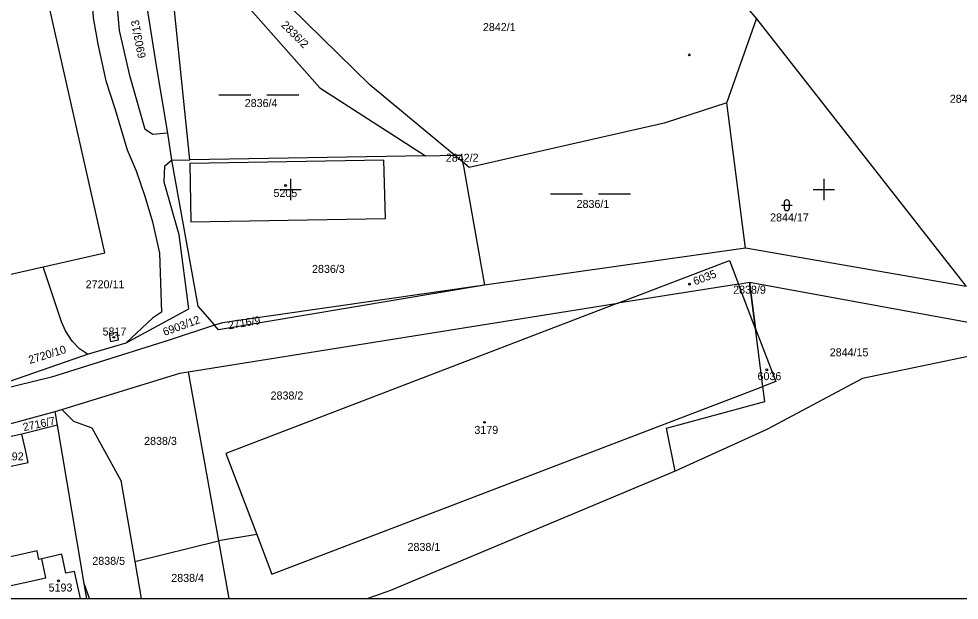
# Model space of a CAD drawing. Extents: x -800194 to -799078, y -1007177 to -1006597.
# Drawn here: x -799850.9 to -799674.6, y -1007177 to -1007068 of the extents above; entities that cross this region are included whole.
import ezdxf

# ---------------------------------------------------------------- set-up
doc = ezdxf.new("R2010")
doc.units = 0
for name, color, linetype in [('Legenda 1', 7, 'Continuous'), ('Ramove udaje', 7, 'Continuous'), ('Vrstva 49', 7, 'Continuous'), ('Vrstva 53', 7, 'Continuous'), ('Vrstva 55', 7, 'Continuous'), ('Vrstva 56', 7, 'Continuous'), ('Vrstva 57', 7, 'Continuous'), ('Vrstva 58', 7, 'Continuous'), ('Vrstva 59', 7, 'Continuous')]:
    doc.layers.add(name, color=color, linetype=linetype)

msp = doc.modelspace()

# ---------------------------------------------------------------- linework, layer by layer
at = {"layer": 'Legenda 1'}
msp.add_lwpolyline([(-800193.4, -1007176.65), (-799312.4, -1007176.65), (-799312.4, -1006766.65), (-800193.4, -1006766.65)], close=True, dxfattribs=at)
at = {"layer": 'Ramove udaje'}
for p, q in [((-799800, -1007098), (-799800, -1007102)), ((-799700, -1007098), (-799700, -1007102)), ((-799802, -1007100), (-799800, -1007100)), ((-799800, -1007100), (-799798, -1007100)), ((-799702, -1007100), (-799700, -1007100)), ((-799700, -1007100), (-799698, -1007100))]:
    msp.add_line(p, q, dxfattribs=at)
at = {"layer": 'Vrstva 49'}
for p, q in [((-799725.4, -1007074.54), (-799725.05, -1007074.89)), ((-799725.4, -1007074.89), (-799725.05, -1007074.54))]:
    msp.add_line(p, q, dxfattribs=at)
at = {"layer": 'Vrstva 53'}
for points in [[(-799673.33, -1007118.14), (-799714.71, -1007110.97), (-799718.21, -1007083.69), (-799729.93, -1007087.54), (-799766.47, -1007095.84), (-799767.73, -1007094.8), (-799769.22, -1007093.56), (-799785.06, -1007080.42), (-799809.11, -1007056.81), (-799818.59, -1007034.4), (-799822.79, -1007029.13), (-799826.14, -1007024.13), (-799830.75, -1006966.73), (-799839.73, -1006961.33), (-799877.87, -1006942.17), (-799936.47, -1006903.99), (-799954.76, -1006895.45), (-799964.79, -1006890.84)], [(-799662.13, -1007129.03), (-799692.74, -1007135.4), (-799710.71, -1007144.99), (-799727.84, -1007152.76), (-799729.51, -1007144.72), (-799711.04, -1007139.72), (-799711.41, -1007136.88), (-799712.8, -1007126.1), (-799713.93, -1007117.37), (-799664.74, -1007126.35)]]:
    msp.add_lwpolyline(points, dxfattribs=at)
at = {"layer": 'Vrstva 55'}
for p, q in [((-799818.85, -1007094.38), (-799825.16, -1007033.58)), ((-799727.16, -1007050.52), (-799712.65, -1007067.97)), ((-799718.21, -1007083.69), (-799712.65, -1007067.97)), ((-799712.65, -1007067.97), (-799673.33, -1007118.14)), ((-799714.71, -1007110.97), (-799718.21, -1007083.69)), ((-799823.03, -1007089.38), (-799822.31, -1007094.44)), ((-799774.66, -1007093.65), (-799818.85, -1007094.38)), ((-799774.66, -1007093.65), (-799769.22, -1007093.56)), ((-799767.73, -1007094.8), (-799769.22, -1007093.56)), ((-799822.31, -1007094.44), (-799818.85, -1007094.38)), ((-799714.71, -1007110.97), (-799763.63, -1007117.94)), ((-799673.33, -1007118.14), (-799714.71, -1007110.97)), ((-799853.26, -1007116.03), (-799846.34, -1007114.47)), ((-799716.02, -1007117.7), (-799738.61, -1007121.3)), ((-799716.02, -1007117.7), (-799713.93, -1007117.37)), ((-799712.8, -1007126.1), (-799716.02, -1007117.7)), ((-799713.93, -1007117.37), (-799664.74, -1007126.35)), ((-799713.93, -1007117.37), (-799712.8, -1007126.1)), ((-799819.2, -1007134.15), (-799738.61, -1007121.3)), ((-799711.41, -1007136.88), (-799712.8, -1007126.1)), ((-799838.05, -1007130.83), (-799830.82, -1007128.75)), ((-799853.69, -1007136.27), (-799838.05, -1007130.83)), ((-799819.2, -1007134.15), (-799813.5, -1007165.83)), ((-799803.46, -1007172.11), (-799711.41, -1007136.88)), ((-799902.49, -1007157.51), (-799844.11, -1007141.59)), ((-799844.11, -1007141.59), (-799842.89, -1007141.21)), ((-799843.67, -1007144.18), (-799844.11, -1007141.59)), ((-799842.89, -1007141.21), (-799840.66, -1007143.43)), ((-799843.67, -1007144.18), (-799850.35, -1007145.84)), ((-799850.35, -1007145.84), (-799857.1, -1007147.35)), ((-799727.84, -1007152.76), (-799781.23, -1007175.14)), ((-799831.81, -1007154.54), (-799829.18, -1007169.73)), ((-799806.31, -1007164.66), (-799813.5, -1007165.83)), ((-799806.31, -1007164.66), (-799803.46, -1007172.11)), ((-799829.18, -1007169.73), (-799813.5, -1007165.83)), ((-799813.5, -1007165.83), (-799811.57, -1007176.65)), ((-799829.18, -1007169.73), (-799827.98, -1007176.65)), ((-799837.65, -1007176.65), (-799838.65, -1007173.83)), ((-799781.23, -1007175.14), (-799785.48, -1007176.65))]:
    msp.add_line(p, q, dxfattribs=at)
for points in [[(-799769.22, -1007093.56), (-799785.06, -1007080.42), (-799809.11, -1007056.81), (-799818.59, -1007034.4), (-799822.79, -1007029.13)], [(-799825.16, -1007033.58), (-799811.39, -1007061.77), (-799794.49, -1007080.93), (-799774.66, -1007093.65)], [(-799823.03, -1007089.38), (-799825.77, -1007089.63), (-799827.26, -1007088.72), (-799830.02, -1007078.85), (-799832.03, -1007070.18), (-799833.02, -1007058.82), (-799832.71, -1007046.42)], [(-799831.14, -1007046.62), (-799828.75, -1007046.93), (-799828.27, -1007056.97), (-799826.13, -1007070.87), (-799825.16, -1007076.77), (-799823.03, -1007089.38)], [(-799858.84, -1007065.67), (-799858.76, -1007060.77), (-799858.72, -1007059.86), (-799857.59, -1007058.97), (-799845.38, -1007056.13), (-799841.77, -1007056.79), (-799839.5, -1007058.21), (-799837.43, -1007060.68), (-799836.99, -1007067.77), (-799836.14, -1007072.71), (-799834.61, -1007079.6), (-799832.83, -1007084.94), (-799830.58, -1007092.52), (-799828.9, -1007096.44), (-799827.32, -1007101.2), (-799825.89, -1007106.02), (-799824.52, -1007111.92), (-799824.25, -1007121.19), (-799824.17, -1007122.98), (-799825.87, -1007124.09), (-799830.82, -1007128.75)], [(-799846.34, -1007114.47), (-799834.79, -1007111.87), (-799845.89, -1007062.76), (-799858.84, -1007065.67)], [(-799718.21, -1007083.69), (-799729.93, -1007087.54), (-799766.47, -1007095.84), (-799767.73, -1007094.8)], [(-799769.22, -1007093.56), (-799767.95, -1007093.54), (-799767.73, -1007094.8)], [(-799830.82, -1007128.75), (-799819.06, -1007122.35), (-799820.88, -1007108.46), (-799823.65, -1007098.62), (-799823.55, -1007095.54), (-799822.31, -1007094.44)], [(-799822.31, -1007094.44), (-799817.36, -1007121.82), (-799814.24, -1007125.43)], [(-799782.48, -1007094.48), (-799818.89, -1007095.11), (-799818.65, -1007106.02), (-799782.2, -1007105.4), (-799782.48, -1007094.48)], [(-799767.73, -1007094.8), (-799767.52, -1007095.98), (-799763.63, -1007117.94)], [(-799738.61, -1007121.3), (-799717.71, -1007113.29), (-799716.02, -1007117.7)], [(-799838.05, -1007130.83), (-799839.52, -1007129.85), (-799840.91, -1007128.4), (-799842.17, -1007126.45), (-799842.9, -1007124.78), (-799846.34, -1007114.47)], [(-799763.63, -1007117.94), (-799813.49, -1007126.3), (-799814.24, -1007125.43)], [(-799763.63, -1007117.94), (-799812.76, -1007124.95), (-799814.24, -1007125.43)], [(-799738.61, -1007121.3), (-799812.11, -1007149.49), (-799806.31, -1007164.66)], [(-799814.24, -1007125.43), (-799822.76, -1007128.21), (-799844.82, -1007135.16), (-799895.02, -1007147.45)], [(-799832.49, -1007126.78), (-799834.01, -1007127.06), (-799833.76, -1007128.46), (-799832.24, -1007128.15), (-799832.49, -1007126.78)], [(-799712.8, -1007126.1), (-799709.02, -1007135.97), (-799711.41, -1007136.88)], [(-799662.13, -1007129.03), (-799692.74, -1007135.4), (-799710.71, -1007144.99), (-799727.84, -1007152.76)], [(-799842.89, -1007141.21), (-799820.76, -1007134.4), (-799819.2, -1007134.15)], [(-799727.84, -1007152.76), (-799729.51, -1007144.72), (-799711.04, -1007139.72), (-799711.41, -1007136.88)], [(-799840.66, -1007143.43), (-799837.23, -1007144.63), (-799831.81, -1007154.54)], [(-799838.65, -1007173.83), (-799839.02, -1007171.64), (-799839.09, -1007171.24), (-799843.67, -1007144.18)], [(-799855.94, -1007152.6), (-799849.17, -1007151.19), (-799849.68, -1007148.8), (-799850.35, -1007145.84)], [(-799839.36, -1007176.65), (-799840.49, -1007171.57), (-799842.09, -1007171.9), (-799842.85, -1007168.35), (-799846.6, -1007169.23), (-799847.19, -1007169.37), (-799847.51, -1007167.75), (-799861.36, -1007170.85), (-799866.14, -1007171.83), (-799865.33, -1007175.48), (-799865.03, -1007176.65)], [(-799838.17, -1007176.65), (-799838.65, -1007173.83)]]:
    msp.add_lwpolyline(points, dxfattribs=at)
at = {"layer": 'Vrstva 56'}
for p, q in [((-799845.85, -1007172.76), (-799846.6, -1007169.23)), ((-799864.94, -1007176.98), (-799845.85, -1007172.76))]:
    msp.add_line(p, q, dxfattribs=at)
at = {"layer": 'Vrstva 58'}
for p, q in [((-799813.4, -1007082.19), (-799807.4, -1007082.19)), ((-799804.4, -1007082.19), (-799798.4, -1007082.19)), ((-799751.26, -1007100.77), (-799745.26, -1007100.77)), ((-799742.26, -1007100.77), (-799736.26, -1007100.77)), ((-799707.94, -1007102.93), (-799705.93, -1007102.93)), ((-799707.44, -1007102.43), (-799707.44, -1007103.43)), ((-799706.43, -1007103.43), (-799706.43, -1007102.43))]:
    msp.add_line(p, q, dxfattribs=at)
for centre, start, end in [((-799706.93, -1007102.43), 0, 180), ((-799706.93, -1007103.43), 180, 359.9879)]:
    msp.add_arc(centre, 0.5, start, end, dxfattribs=at)
at = {"layer": 'Vrstva 59'}
for centre in [(-799800.9, -1007099.21), (-799725.21, -1007117.73), (-799833.12, -1007127.69), (-799710.71, -1007133.78), (-799763.59, -1007143.63), (-799843.49, -1007173.35)]:
    msp.add_circle(centre, 0.175, dxfattribs=at)

# ---------------------------------------------------------------- texts
at = {"layer": 'Vrstva 57'}
for s, rotation, p in [('6903/13', 101, (-799827.08, -1007075.21)), ('2836/2', 315, (-799801.84, -1007069.26)), ('6035', 21, (-799724.15, -1007117.96)), ('6903/12', 20, (-799823.6, -1007127.45)), ('2716/9', 9.6773, (-799811.58, -1007126.21)), ('2720/10', 17, (-799848.86, -1007132.7)), ('2716/7', 12, (-799849.99, -1007145.29))]:
    msp.add_text(s, height=1.5, rotation=rotation, dxfattribs=at).set_placement(p)
for s, p in [('2842/1', (-799763.91, -1007070.26)), ('2836/4', (-799808.57, -1007084.51)), ('2844/77', (-799676.38, -1007083.71)), ('2842/2', (-799770.87, -1007094.76)), ('5205', (-799803.18, -1007101.38)), ('2836/1', (-799746.35, -1007103.43)), ('2844/17', (-799710.07, -1007105.96)), ('2836/3', (-799795.95, -1007115.61)), ('2720/11', (-799838.38, -1007118.5)), ('2838/9', (-799717, -1007119.51)), ('5817', (-799835.22, -1007127.35)), ('2844/15', (-799698.89, -1007131.25)), ('6036', (-799712.43, -1007135.72)), ('2838/2', (-799803.72, -1007139.35)), ('3179', (-799765.51, -1007145.79)), ('2838/3', (-799827.43, -1007147.86)), ('5192', (-799854.48, -1007150.76)), ('2838/1', (-799778.04, -1007167.74)), ('2838/5', (-799837.14, -1007170.35)), ('2838/4', (-799822.34, -1007173.55)), ('5193', (-799845.34, -1007175.36))]:
    msp.add_text(s, height=1.5, dxfattribs=at).set_placement(p)

doc.saveas('drawing.dxf')
